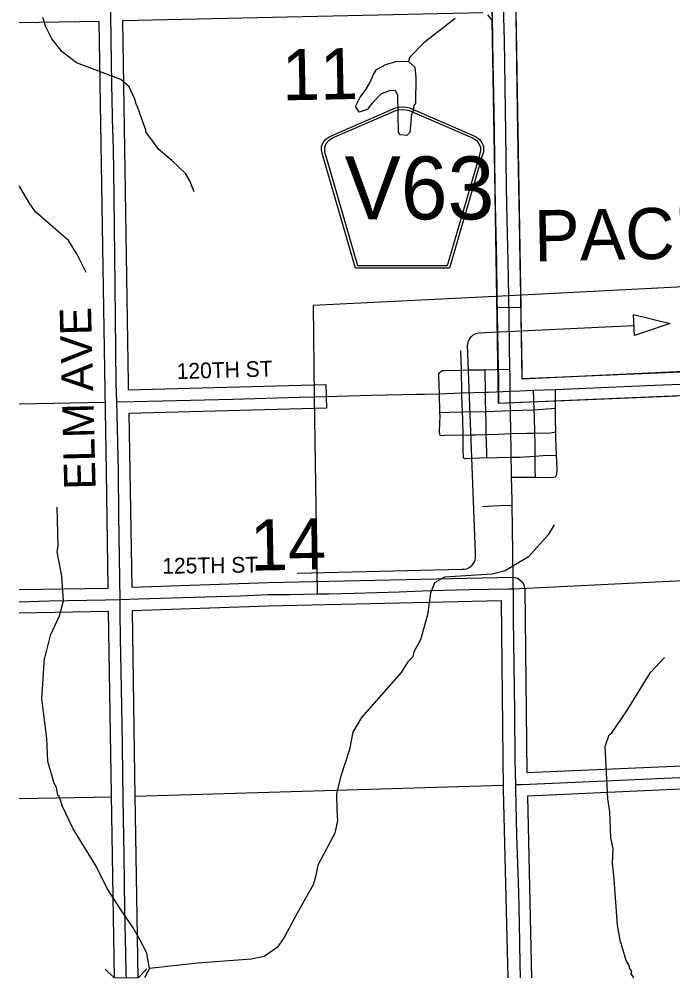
# Model space of a CAD drawing. Extents: x 10133 to 81668, y 7924 to 11018.
# Drawn here: x 10954.9 to 11204.3, y 8510.5 to 8876.1 of the extents above; entities that cross this region are included whole.
import ezdxf

# ---------------------------------------------------------------- set-up
doc = ezdxf.new("R2010")
doc.units = 0
for name, color, linetype in [('tdCoCityStreetMajor', 7, 'Continuous'), ('tdCoCityStreetMinor', 7, 'Continuous'), ('tdCoCoBndryPart', 7, 'Continuous'), ('tdCoCoBndryTxt', 7, 'Continuous'), ('tdCoCorpPopTxt', 7, 'Continuous'), ('tdCoDirctArrow', 7, 'Continuous'), ('tdCoHydroRiver', 7, 'Continuous'), ('tdCoPriNonDiv', 7, 'Continuous'), ('tdCoRROwnerTxt', 7, 'Continuous'), ('tdCoSecRteBand', 7, 'Continuous'), ('tdCoShieldCoRte', 7, 'Continuous'), ('tdCoShieldStRte', 7, 'Continuous'), ('tdCoStrucNonDivPri', 7, 'Continuous'), ('tdCoSurfAsphalt', 7, 'Continuous'), ('tdCoSurfEarth', 7, 'Continuous'), ('tdCoSurfGravel', 7, 'Continuous'), ('tdCoTwpBndryShd', 7, 'Continuous'), ('tdCoUnicrpTwnTxt', 7, 'Continuous')]:
    doc.layers.add(name, color=color, linetype=linetype)

msp = doc.modelspace()

# ---------------------------------------------------------------- linework, layer by layer
at = {"layer": 'tdCoCityStreetMajor'}
for points in [[(10992.13, 8730.16), (10991.93, 8737.17), (10991.63, 8762.47), (10991.34, 8786.04), (10990.97, 8818.92), (10990.89, 8825.73), (10990.69, 8831.6)], [(10992.13, 8730.16), (10998.76, 8730.28), (11036.45, 8731.24)], [(10993.41, 8654.83), (10993.3, 8662.67), (10992.93, 8686.97), (10992.74, 8703.62), (10992.56, 8715.01), (10992.13, 8730.16)]]:
    msp.add_lwpolyline(points, dxfattribs=at)
at = {"layer": 'tdCoCityStreetMinor'}
for points in [[(10990.69, 8831.6), (10990.63, 8833.31), (10990.23, 8851.4), (10990.01, 8868.27), (10989.82, 8878.03), (10989.79, 8879.9)], [(11036.45, 8731.24), (11061.57, 8732.02), (11067.49, 8732.16)], [(10995.77, 8510.55), (10995.74, 8512.15), (10995.55, 8519.85), (10995.26, 8536.42), (10995.11, 8546.74), (10994.96, 8557.5), (10994.7, 8571.08), (10994.41, 8587.87), (10994.26, 8599.49), (10993.89, 8620.98), (10993.59, 8640.25), (10993.48, 8649.65), (10993.41, 8654.83)], [(11144.19, 8584.21), (11146.72, 8584.21), (11166.99, 8585.1), (11192.55, 8586.28), (11218.41, 8587.46), (11243.97, 8588.72), (11258.54, 8589.28), (11282.47, 8590.39), (11291.46, 8590.39), (11295.44, 8590.24)]]:
    msp.add_lwpolyline(points, dxfattribs=at)
at = {"layer": 'tdCoCoBndryPart'}
msp.add_lwpolyline([(11142.2, 8734.26), (11146.06, 8734.43), (11151.11, 8734.63), (11159.46, 8734.96), (11168.15, 8735.32), (11194.35, 8736.41), (11216.71, 8737.34)], dxfattribs=at)
at = {"layer": 'tdCoCorpPopTxt'}
for points in [[(11123.58, 8742.34), (11123.42, 8749.68)], [(11115.43, 8726.16), (11115.2, 8733.31), (11114.98, 8739.99), (11115.02, 8740.84), (11115.21, 8741.21), (11115.65, 8741.69), (11115.74, 8741.74), (11116.35, 8742.1), (11117.09, 8742.21), (11123.58, 8742.34)], [(11123.58, 8742.34), (11126.49, 8742.39), (11132.65, 8742.46)], [(11124.04, 8726.38), (11123.79, 8732.78), (11123.77, 8733.58), (11123.58, 8742.34)], [(11132.65, 8742.46), (11136.66, 8742.5), (11142.14, 8742.63)], [(11132.89, 8726.52), (11132.78, 8730.63), (11132.74, 8733.87), (11132.74, 8733.87), (11132.65, 8742.46)], [(11151.39, 8727.18), (11151.11, 8734.63)], [(11159.52, 8727.75), (11159.46, 8734.96)], [(11132.89, 8726.52), (11133.18, 8726.52), (11142.3, 8726.84), (11151.09, 8727.15), (11151.39, 8727.18)], [(11151.39, 8727.18), (11159.52, 8727.75)], [(11151.63, 8718.3), (11151.49, 8724.45), (11151.39, 8727.18)], [(11159.63, 8718.73), (11159.56, 8723.49), (11159.52, 8727.75)], [(11124.22, 8717.53), (11124.21, 8717.53), (11117.39, 8717.31), (11116.28, 8717.2), (11115.69, 8717.35), (11115.5, 8717.5), (11115.42, 8717.75), (11115.32, 8718.05), (11115.28, 8718.9), (11115.46, 8725.05), (11115.43, 8726.16)], [(11115.43, 8726.16), (11119.2, 8726.3), (11124.04, 8726.38)], [(11124.04, 8726.38), (11124.1, 8726.38), (11132.89, 8726.52)], [(11124.22, 8717.53), (11124.16, 8723.57), (11124.04, 8726.38)], [(11133.1, 8717.8), (11133, 8722.38), (11132.89, 8726.52)], [(11124.22, 8717.53), (11127.49, 8717.63), (11129.04, 8717.68), (11133.1, 8717.8)], [(11133.28, 8708.85), (11125.05, 8708.47), (11124.68, 8708.47), (11124.61, 8708.61), (11124.54, 8708.75), (11124.42, 8708.99), (11124.27, 8712.28), (11124.22, 8717.53)], [(11133.1, 8717.8), (11137.79, 8717.93), (11142.5, 8718.07), (11148.39, 8718.24), (11151.63, 8718.3)], [(11133.28, 8708.85), (11133.26, 8710.95), (11133.1, 8717.8)], [(11151.63, 8718.3), (11157.56, 8718.42), (11159.63, 8718.73)], [(11151.75, 8709.54), (11151.72, 8714.24), (11151.63, 8718.3)], [(11159.89, 8709.85), (11159.67, 8716.54), (11159.63, 8718.73)], [(11133.28, 8708.85), (11137.25, 8709.03), (11142.65, 8709.1), (11142.65, 8709.1), (11145.58, 8709.14), (11151.75, 8709.54)], [(11151.75, 8709.54), (11154.64, 8709.73), (11159.89, 8709.85)], [(11151.86, 8701.45), (11151.79, 8704.18), (11151.75, 8709.54)], [(11151.86, 8701.45), (11157.41, 8701.41), (11158.89, 8701.48), (11159.41, 8701.59), (11159.78, 8701.93), (11159.92, 8702.26), (11160.04, 8702.55), (11160.15, 8704.33), (11159.96, 8707.51), (11159.89, 8709.85)], [(11142.76, 8701.53), (11146.94, 8701.48), (11151.86, 8701.45)], [(11131.59, 8690.23), (11135.73, 8690.56), (11138.58, 8690.63), (11142.98, 8690.86)]]:
    msp.add_lwpolyline(points, dxfattribs=at)
at = {"layer": 'tdCoDirctArrow'}
msp.add_lwpolyline([(11189.22, 8763.57), (11203.27, 8760.14), (11189.68, 8755.49)], close=True, dxfattribs=at)
msp.add_lwpolyline([(11060.94, 8664.91), (11123.92, 8666.39), (11124.68, 8666.37), (11125.67, 8666.58), (11126.81, 8667.11), (11127.71, 8667.87), (11128.34, 8668.76), (11128.82, 8669.71), (11129.03, 8670.77), (11128.98, 8672.58), (11125.96, 8751.86), (11126.12, 8752.74), (11126.33, 8753.53), (11126.86, 8754.41), (11127.49, 8755.18), (11127.93, 8755.59), (11128.83, 8756.08), (11129.64, 8756.4), (11130.36, 8756.54), (11131.1, 8756.59), (11131.98, 8756.54), (11132.77, 8756.59), (11189.41, 8759.35)], dxfattribs=at)
at = {"layer": 'tdCoHydroRiver'}
msp.add_line((11004.61, 8514.13), (11002.65, 8510.55), dxfattribs=at)
for points in [[(11021.65, 8810.29), (11019.92, 8814.76), (11018.46, 8817.1), (11013.16, 8822.22), (11008.12, 8826.4), (11005.7, 8829.68), (11003.27, 8833.19), (11003.25, 8834.13), (11002.77, 8834.84), (11000.03, 8842.84), (10999.54, 8843.78), (10999.03, 8845.67), (10996.82, 8850.36), (10993.7, 8853.15), (10976.78, 8859.5), (10971.26, 8863.67), (10967.39, 8868.58), (10964.94, 8873.51), (10964.19, 8876.1), (10963.94, 8876.81)], [(11121.18, 8876.37), (11109.26, 8867.17), (11103.9, 8861.63), (11103.46, 8859.97)], [(11103.46, 8859.97), (11105.86, 8857.88), (11106.16, 8853.86), (11106.09, 8844.15), (11105.4, 8843.19), (11105.2, 8841.05), (11104.5, 8839.86), (11103.91, 8832.98), (11102.75, 8831.78), (11100.38, 8831.97), (11099.65, 8832.91), (11099.41, 8847.11), (11098.44, 8848.76), (11096.54, 8848.96), (11093.01, 8847.72), (11089.52, 8844.11), (11087.66, 8841.71), (11084.6, 8840.71), (11083.14, 8842.82), (11084.98, 8846.4), (11087.06, 8849.04), (11088.67, 8851.91), (11090.04, 8855.01), (11091.2, 8856.92), (11094.71, 8858.87), (11098.96, 8860.13), (11103.46, 8859.97)], [(10980.49, 8779.52), (10977.06, 8786.33), (10973.66, 8791.72), (10961.16, 8802.64), (10958.98, 8805.68), (10955.08, 8812.25), (10954.88, 8812.66)], [(10969.2, 8690.06), (10969.69, 8675.1), (10969.26, 8672.96), (10971.07, 8663.73), (10971.71, 8654.24), (10970.14, 8648.51), (10966.72, 8641.09), (10964.5, 8632.5)], [(11158.99, 8683.3), (11156.69, 8679.47), (11149.25, 8671.06), (11140.34, 8665.7), (11135.39, 8664.43), (11117.13, 8663.34), (11113.37, 8661.13), (11111.77, 8657.3), (11110.71, 8648.98), (11108.01, 8639.43), (11105.47, 8634.87)], [(11004.61, 8514.13), (11003.57, 8519.79), (11001.61, 8524.02), (10998.43, 8529.65), (10994.07, 8535.97), (10988.47, 8544.64), (10984.31, 8553.09), (10975.54, 8567.39), (10971.38, 8575.85), (10970.12, 8579.85), (10969.65, 8580.08), (10969.12, 8583.15), (10968.14, 8585.04), (10967.64, 8586.93), (10965.87, 8593.08), (10965.49, 8601.86), (10963.57, 8617.04), (10964.5, 8632.5)], [(11105.47, 8634.87), (11105.02, 8632.96), (11103.16, 8631.02), (11100.61, 8626.93), (11085.45, 8609.78), (11082.21, 8604.25), (11080.88, 8597.58), (11077.51, 8587.1), (11075.96, 8580.68), (11076.06, 8574.52), (11076.37, 8570.5), (11075.26, 8565.75), (11068.84, 8553.56), (11067.96, 8549.05), (11067.07, 8545.96), (11060.86, 8534.96), (11056.04, 8525.88), (11053.26, 8522.05), (11048.35, 8518.65), (11043.39, 8517.62), (11023.05, 8516.09), (11004.61, 8514.13)], [(11189.44, 8510.55), (11188.4, 8512.24), (11188.63, 8512.95), (11187.9, 8514.12), (11187.64, 8515.3), (11186.42, 8517.17), (11184.16, 8524.95), (11183.12, 8530.62), (11181.88, 8548.12), (11181.3, 8554.27), (11181.45, 8559.72), (11180.67, 8563.96), (11180.26, 8573.9), (11179.47, 8578.86), (11178.43, 8598.74), (11180.01, 8603.26), (11180.94, 8603.99), (11186.72, 8612.37), (11195.71, 8626.97), (11201.06, 8632.74)]]:
    msp.add_lwpolyline(points, dxfattribs=at)
at = {"layer": 'tdCoPriNonDiv'}
for points in [[(11148.61, 8588.79), (11290.86, 8594.89), (11288.19, 8736.74), (11212.46, 8732.6), (11211.97, 8741.59), (11288.07, 8745.74), (11286.31, 8865.85), (11285.73, 8888.14)], [(11131.79, 8878.5), (10994.37, 8875.49), (10996.43, 8737.26), (10996.5, 8734.74), (11071.88, 8736.76), (11072.09, 8727.77), (10996.75, 8725.75), (10997.84, 8659.47), (11049.83, 8661.28), (11143.24, 8663.39), (11145.17, 8663.01), (11147.22, 8661.19), (11147.85, 8658.92), (11148.61, 8588.79)], [(11144.31, 8878.21), (11146.22, 8766.24), (11137.22, 8766.08), (11135.36, 8875.7), (11133.63, 8877.74)], [(10954.88, 8658.58), (10988.85, 8659.2), (10988.24, 8703.56), (10985.37, 8875.31), (10954.88, 8874.76)], [(11141.41, 8510.55), (11139.72, 8582.39), (11138.88, 8654.3), (11049.94, 8652.28), (10997.97, 8650.47), (10998.9, 8587.94), (11000.2, 8510.55)], [(10991.29, 8510.55), (10988.97, 8650.2), (10954.88, 8649.58)], [(11291.82, 8510.55), (11291.02, 8585.89), (11282.58, 8585.89), (11148.78, 8579.8), (11150.34, 8510.55)]]:
    msp.add_lwpolyline(points, dxfattribs=at)
at = {"layer": 'tdCoSecRteBand'}
for points in [[(11141.64, 8770.66), (11141.4, 8783.7), (11141.11, 8799.72), (11140.85, 8812.11), (11140.55, 8833.3), (11140.41, 8841.11), (11140.11, 8859.71), (11140, 8867.85), (11139.84, 8876.96), (11139.81, 8878.28), (11139.8, 8879.28)], [(10954.88, 8653.9), (10966.3, 8654.26), (10987.8, 8654.67), (10993.41, 8654.83), (11000.41, 8655.04), (11025.79, 8655.82), (11039.32, 8656.26), (11049.83, 8656.78), (11058.12, 8656.78), (11068.57, 8656.96), (11069.54, 8656.98), (11073.06, 8657.04), (11082.86, 8657.3), (11099.88, 8657.81), (11111.83, 8658.26), (11126.77, 8658.59), (11141.6, 8658.85), (11143.35, 8658.9), (11143.41, 8647.2), (11143.48, 8638.84), (11143.78, 8620.89), (11143.85, 8612.24), (11144.04, 8593.37), (11144.19, 8584.21), (11144.22, 8582.46), (11144.63, 8564.96), (11145.37, 8543.03), (11145.66, 8531.45), (11145.92, 8515.88), (11146.05, 8510.55)]]:
    msp.add_lwpolyline(points, dxfattribs=at)
at = {"layer": 'tdCoShieldCoRte'}
for p, q in [((10987.7, 8513.8), (10991.07, 8510.55)), ((10991.46, 8510.55), (11000.46, 8510.71))]:
    msp.add_line(p, q, dxfattribs=at)
msp.add_lwpolyline([(11003.65, 8514.01), (11000.46, 8510.71), (11000.46, 8510.55)], dxfattribs=at)
at = {"layer": 'tdCoStrucNonDivPri'}
for p, q in [((10954.88, 8729.46), (10987.6, 8730.08)), ((10954.88, 8578.99), (10990.14, 8579.59))]:
    msp.add_line(p, q, dxfattribs=at)
msp.add_lwpolyline([(10999.04, 8579.8), (11139.7, 8584.07)], dxfattribs=at)
at = {"layer": 'tdCoSurfAsphalt'}
msp.add_lwpolyline([(11132.89, 9033.19), (11132.88, 9035.44), (11141.88, 9035.44), (11146.71, 8738.97), (11294.17, 8746), (11308.79, 8746.04), (11334.35, 8746.15), (11366.91, 8746.3), (11391.58, 8746.26), (11425.21, 8746.56), (11449.9, 8746.78), (11483.73, 8746.82), (11483.73, 8737.82), (11483.67, 8737.82), (11449.95, 8737.78), (11425.29, 8737.56), (11391.61, 8737.26), (11366.93, 8737.3), (11334.39, 8737.15), (11308.82, 8737.04), (11294.37, 8737), (11219.06, 8732.98), (11137.76, 8729.58)], close=True, dxfattribs=at)
for points in [[(11135.3, 8879.22), (11135.31, 8878.21), (11135.5, 8867.78), (11135.61, 8859.65), (11135.91, 8841.03), (11136.05, 8833.23), (11136.35, 8812.03), (11136.61, 8799.63), (11136.9, 8783.62), (11137.14, 8770.58)], [(11135.32, 8879.23), (11135.34, 8878.23), (11135.52, 8867.79), (11135.63, 8859.66), (11135.93, 8841.04), (11136.08, 8833.24), (11136.37, 8812.04), (11136.63, 8799.64), (11136.93, 8783.63), (11137.17, 8770.59)], [(11144.3, 8879.35), (11144.31, 8878.35), (11144.5, 8867.92), (11144.61, 8859.78), (11144.9, 8841.19), (11145.05, 8833.38), (11145.35, 8812.19), (11145.61, 8799.8), (11145.9, 8783.78), (11146.14, 8770.74)], [(11144.32, 8879.36), (11144.34, 8878.37), (11144.52, 8867.94), (11144.63, 8859.79), (11144.93, 8841.2), (11145.08, 8833.39), (11145.37, 8812.2), (11145.63, 8799.82), (11145.93, 8783.79), (11146.16, 8770.75)], [(11137.14, 8770.58), (11137.64, 8742.54), (11137.68, 8740.33), (11137.72, 8730.37), (11137.74, 8729.59)], [(11137.17, 8770.59), (11137.66, 8742.55), (11137.71, 8740.34), (11137.74, 8730.38), (11137.76, 8729.6)], [(11146.14, 8770.74), (11146.64, 8742.71), (11146.68, 8740.43), (11146.69, 8738.95)], [(11146.16, 8770.75), (11146.66, 8742.72), (11146.7, 8740.44), (11146.71, 8738.97)], [(11216.52, 8741.84), (11159.28, 8739.46), (11146.71, 8738.96)], [(11216.51, 8741.85), (11159.3, 8739.47), (11146.73, 8738.97)], [(11216.89, 8732.85), (11159.64, 8730.46), (11146.24, 8729.93), (11137.74, 8729.57)], [(11221.16, 8733.04), (11159.67, 8730.48), (11146.27, 8729.94), (11137.76, 8729.58)]]:
    msp.add_lwpolyline(points, dxfattribs=at)
at = {"layer": 'tdCoSurfEarth'}
msp.add_lwpolyline([(11143.35, 8658.9), (11143.33, 8663.14), (11143.07, 8682.08), (11142.98, 8690.86), (11142.96, 8692.85), (11142.76, 8701.53), (11142.7, 8704.06), (11142.65, 8709.1), (11142.62, 8712.53), (11142.5, 8718.07), (11142.3, 8726.84), (11142.22, 8730.43), (11142.2, 8734.26), (11142.18, 8740.38), (11142.14, 8742.63), (11141.64, 8770.66)], dxfattribs=at)
at = {"layer": 'tdCoSurfGravel'}
msp.add_lwpolyline([(11215.88, 8774.39), (11141.64, 8770.66), (11066.99, 8766.91), (11067.49, 8732.16), (11068.57, 8656.96), (11069.54, 8656.98), (11073.06, 8657.04), (11082.86, 8657.3), (11099.88, 8657.81), (11111.83, 8658.26), (11126.77, 8658.59), (11141.64, 8658.85), (11143.35, 8658.9), (11218.36, 8662.6), (11216.71, 8737.34)], close=True, dxfattribs=at)
at = {"layer": 'tdCoTwpBndryShd'}
msp.add_lwpolyline([(11067.49, 8732.16), (11089.31, 8732.72), (11106.48, 8733.07), (11109.55, 8733.13), (11115.2, 8733.31), (11123.77, 8733.58), (11123.77, 8733.58), (11132.74, 8733.87), (11133.93, 8733.91), (11142.2, 8734.26)], dxfattribs=at)
at = {"layer": 'tdCoUnicrpTwnTxt'}
for points in [[(11083.18, 8781.15), (11070.89, 8823.58), (11070.31, 8825.55), (11070.2, 8826.44), (11070.2, 8827.61), (11070.83, 8829.16), (11071.93, 8830.43), (11073.36, 8831.43), (11098.45, 8842.28), (11099.58, 8842.53), (11101.14, 8842.67), (11102.71, 8842.53), (11103.84, 8842.28), (11128.93, 8831.43), (11130.36, 8830.43), (11131.45, 8829.16), (11132.09, 8827.61), (11132.09, 8826.44), (11131.98, 8825.55), (11131.4, 8823.58), (11119.11, 8781.15)], [(11084.06, 8782.1), (11072.1, 8823.39), (11071.54, 8825.28), (11071.44, 8826.13), (11071.44, 8827.26), (11072.05, 8828.74), (11073.09, 8829.96), (11074.47, 8830.92), (11098.56, 8841.34), (11099.64, 8841.58), (11101.14, 8841.71), (11102.65, 8841.58), (11103.73, 8841.34), (11127.82, 8830.92), (11129.19, 8829.96), (11130.24, 8828.74), (11130.85, 8827.26), (11130.85, 8826.13), (11130.75, 8825.28), (11130.19, 8823.39), (11118.23, 8782.1)]]:
    msp.add_lwpolyline(points, close=True, dxfattribs=at)

# ---------------------------------------------------------------- texts
at = {"layer": 'tdCoCoBndryTxt'}
msp.add_text('PACKWOOD', height=19.5, rotation=1.1105, dxfattribs=at).set_placement((11151.51, 8783.76))
at = {"layer": 'tdCoRROwnerTxt'}
for s, rotation, p in [('11', 1.1414, (11055.32, 8845.14)), ('14', 1.1413, (11043.12, 8665.79))]:
    msp.add_text(s, height=19.5, rotation=rotation, dxfattribs=at).set_placement(p)
at = {"layer": 'tdCoShieldStRte'}
for s, height, rotation, p in [('ELM AVE', 12, 91.47, (10984.09, 8696.89)), ('120TH ST', 6, 1.6259, (11015.07, 8738.87)), ('125TH ST', 6, 0.7808, (11009.52, 8664.64))]:
    msp.add_text(s, height=height, rotation=rotation, dxfattribs=at).set_placement(p)
at = {"layer": 'tdCoUnicrpTwnTxt'}
msp.add_text('V63', height=24, dxfattribs=at).set_placement((11079.06, 8799.79))

doc.saveas('drawing.dxf')
